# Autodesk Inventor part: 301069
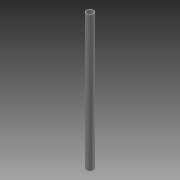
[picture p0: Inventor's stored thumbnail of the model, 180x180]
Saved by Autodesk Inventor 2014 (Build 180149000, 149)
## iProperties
Created: 2007-12
Part Number: 301069
Document SubType Name: Modeling
Designer: TH
Density: 7.85 g/cm^3
Mass: 284.933 g
Surface Area: 485.8 cm^2
Volume: 36.2972 cm^3
Material: Steel
Description: PIVOT BAR
Appearance: Steel
Component Category: Back Component
Author: TH
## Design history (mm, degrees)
sketch "Sketch1"
  geometry: C1 r 10.5 at (0, 0); C2 r 9 at (0, 0); 1 further point
  constraints: 2 centre point, 2 coincident
  dimensions: "d0" = 18 diameter of C2; "d1" = 21 diameter of C1
extrude "Extrusion1" new body sketch "Sketch1" stored distance "d2" = 395; taper "d3" = 0 deg
body "Solid1"
